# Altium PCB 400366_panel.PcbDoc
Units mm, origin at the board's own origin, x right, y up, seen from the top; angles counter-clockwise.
Board outline 266.08 x 131.72 mm, 4 copper layers (Top Layer, Mid-Layer 1, Mid-Layer 2, Bottom Layer), stack 1.516 mm thick; 4 components, 35 nets, 260 pads, 0 vias.
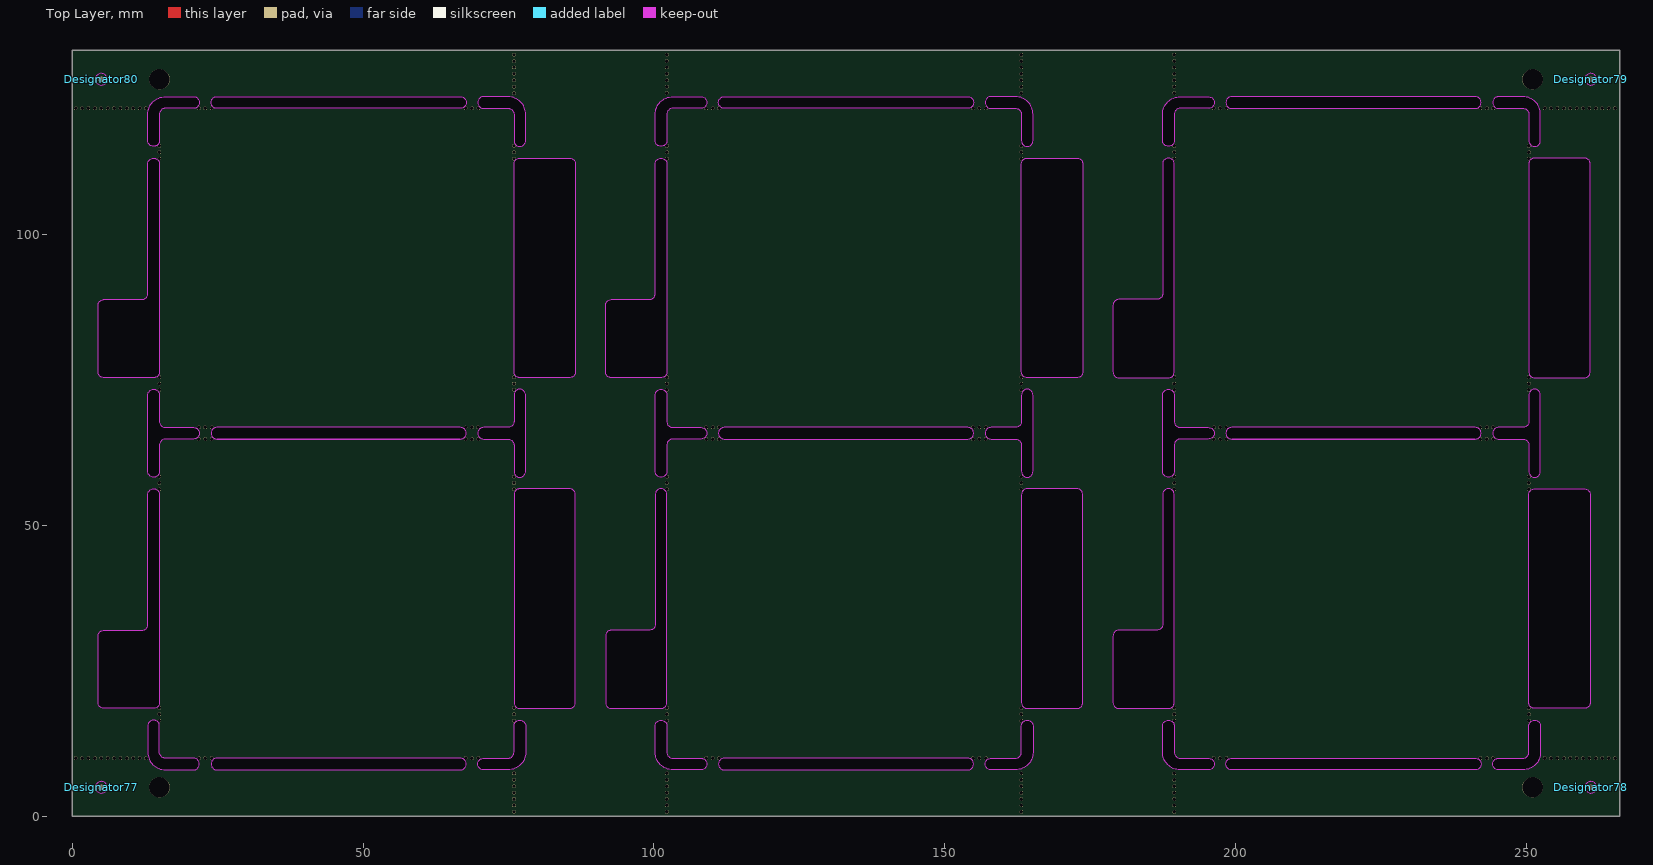
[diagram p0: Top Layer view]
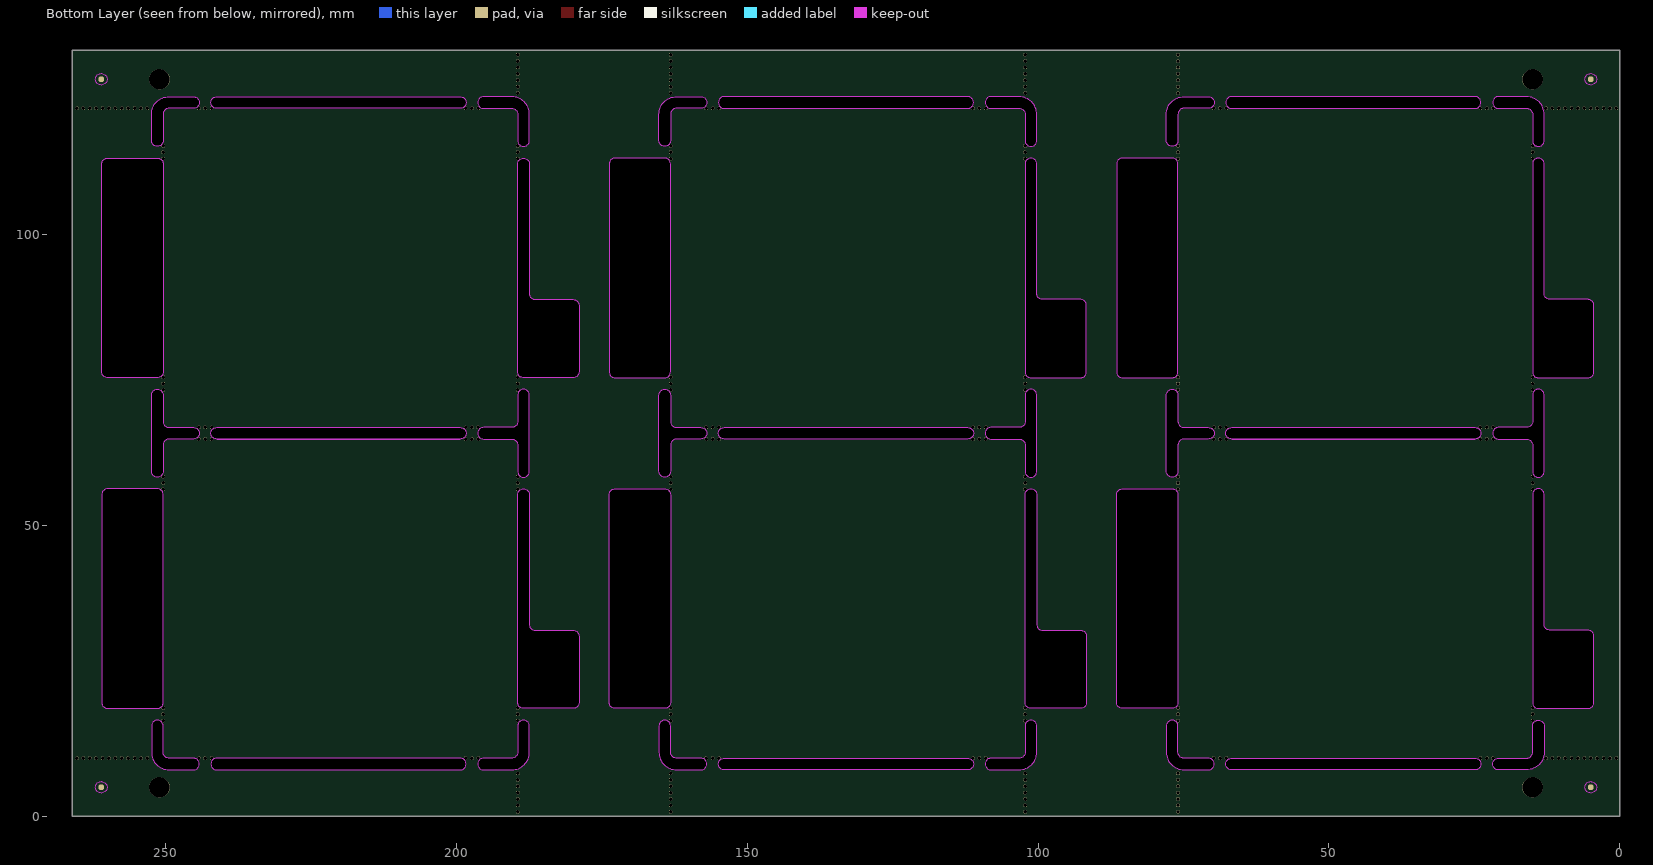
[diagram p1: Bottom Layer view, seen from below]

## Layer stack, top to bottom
Top Solder: solder mask 0.0381, SM-003, Dk 3.4
Top Layer: signal copper 0.0457
Dielectric1: prepreg 0.1626, FR-4, Dk 3.9
Mid-Layer 1: signal copper 0.035
Dielectric2: core 1.029, FR-4, Dk 3.9
Mid-Layer 2: signal copper 0.035
Dielectric3: prepreg 0.1626, FR-4, Dk 3.9
Bottom Layer: signal copper 0.0457
Bottom Solder: solder mask 0.0381, SM-003, Dk 3.4

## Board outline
0,0 266.075,0 266.075,131.725 0,131.725
cut-out: 187.476,116.172 187.476,120.712 cw(c190.492,120.712) 190.492,123.728 195.357,123.728 cw(c195.357,122.728) 195.357,121.728 190.492,121.728 ccw(c190.492,120.712) 189.476,120.712 189.476,116.172 cw(c188.476,116.172)
cut-out: 199.352,121.728 241.217,121.728 ccw(c241.217,122.728) 241.217,123.728 199.352,123.728 ccw(c199.352,122.728)
cut-out: 245.205,121.728 249.42,121.728 cw(c249.42,120.712) 250.436,120.712 250.436,116.172 ccw(c251.436,116.172) 252.436,116.172 252.436,120.712 ccw(c249.42,120.712) 249.42,123.728 245.205,123.728 ccw(c245.205,122.728)
cut-out: 199.352,64.864 241.217,64.864 ccw(c241.217,65.864) 241.217,66.864 199.352,66.864 ccw(c199.352,65.864)
cut-out: 199.352,64.864 241.217,64.864
cut-out: 245.205,64.864 249.42,64.864 cw(c249.42,63.848) 250.436,63.848 250.436,59.308 ccw(c251.436,59.308) 252.436,59.308 252.436,72.418 ccw(c251.436,72.418) 250.436,72.418 250.436,67.88 cw(c249.42,67.88) 249.42,66.864 245.205,66.864 ccw(c245.205,65.864)
cut-out: 250.436,76.414 ccw(c251.436,76.414) 251.436,75.414 259.976,75.414 ccw(c259.976,76.414) 260.976,76.414 260.976,112.176 ccw(c259.976,112.176) 259.976,113.176 251.436,113.176 ccw(c251.436,112.176) 250.436,112.176
cut-out: 250.436,19.55 250.436,55.312 cw(c251.436,55.312) 251.436,56.312 259.976,56.312 cw(c259.976,55.312) 260.976,55.312 260.976,19.55 cw(c259.976,19.55) 259.976,18.55 251.436,18.55 cw(c251.436,19.55)
cut-out: 245.205,8 cw(c245.205,9) 245.205,10 249.42,10 ccw(c249.42,11.016) 250.436,11.016 250.436,15.554 cw(c251.436,15.554) 252.436,15.554 252.436,11.016 cw(c249.42,11.016) 249.42,8
cut-out: 199.352,8 cw(c199.352,9) 199.352,10 241.217,10 cw(c241.217,9) 241.217,8
cut-out: 187.476,11.016 187.476,15.554 cw(c188.476,15.554) 189.476,15.554 189.476,11.016 ccw(c190.492,11.016) 190.492,10 195.356,10 cw(c195.356,9) 195.356,8 190.492,8 cw(c190.492,11.016)
cut-out: 187.476,59.308 187.476,72.418 cw(c188.476,72.418) 189.476,72.418 189.476,67.88 ccw(c190.492,67.88) 190.492,66.864 195.356,66.864 cw(c195.356,65.864) 195.356,64.864 190.492,64.864 ccw(c190.492,63.848) 189.476,63.848 189.476,59.308 cw(c188.476,59.308)
cut-out: 178.936,19.55 ccw(c179.936,19.55) 179.936,18.55 188.476,18.55 ccw(c188.476,19.55) 189.476,19.55 189.476,55.312 ccw(c188.476,55.312) 187.476,55.312 187.476,33 cw(c186.476,33) 186.476,32 179.936,32 ccw(c179.936,31) 178.936,31
cut-out: 178.936,76.414 ccw(c179.936,76.414) 179.936,75.414 188.476,75.414 ccw(c188.476,76.414) 189.476,76.414 189.476,112.176 ccw(c188.476,112.176) 187.476,112.176 187.476,89.864 cw(c186.476,89.864) 186.476,88.864 179.936,88.864 ccw(c179.936,87.864) 178.936,87.864
cut-out: 157.967,64.864 162.182,64.864 cw(c162.182,63.848) 163.198,63.848 163.198,59.308 ccw(c164.198,59.308) 165.198,59.308 165.198,72.419 ccw(c164.198,72.419) 163.198,72.419 163.198,67.88 cw(c162.182,67.88) 162.182,66.864 157.967,66.864 ccw(c157.967,65.864)
cut-out: 112.114,64.864 153.979,64.864 ccw(c153.979,65.864) 153.979,66.864 112.114,66.864 ccw(c112.114,65.864)
cut-out: 70.729,64.864 74.944,64.864 cw(c74.944,63.848) 75.96,63.848 75.96,59.308 ccw(c76.96,59.308) 77.96,59.308 77.96,72.419 ccw(c76.96,72.419) 75.96,72.419 75.96,67.88 cw(c74.944,67.88) 74.944,66.864 70.729,66.864 ccw(c70.729,65.864)
cut-out: 24.876,64.864 66.741,64.864 ccw(c66.741,65.864) 66.741,66.864 24.876,66.864 ccw(c24.876,65.864)
cut-out: 100.238,59.308 100.238,72.419 cw(c101.238,72.419) 102.238,72.419 102.238,67.88 ccw(c103.254,67.88) 103.254,66.864 108.118,66.864 cw(c108.118,65.864) 108.118,64.864 103.254,64.864 ccw(c103.254,63.848) 102.238,63.848 102.238,59.308 cw(c101.238,59.308)
cut-out: 92.698,75.415 cw(c92.698,76.415) 91.698,76.415 91.698,87.864 cw(c92.698,87.864) 92.698,88.864 99.238,88.864 ccw(c99.238,89.864) 100.238,89.864 100.238,112.176 cw(c101.238,112.176) 102.238,112.176 102.238,76.415 cw(c101.238,76.415) 101.238,75.415
cut-out: 100.238,116.172 100.238,120.712 cw(c103.254,120.712) 103.254,123.728 103.254,123.729 108.119,123.729 cw(c108.119,122.728) 108.119,121.728 103.254,121.728 ccw(c103.254,120.712) 102.238,120.712 102.238,116.172 cw(c101.238,116.172)
cut-out: 112.114,121.728 cw(c112.114,122.728) 112.114,123.729 112.114,123.728 153.979,123.729 cw(c153.979,122.728) 153.979,121.728
cut-out: 157.967,121.728 162.182,121.728 cw(c162.182,120.712) 163.198,120.712 163.198,116.172 ccw(c164.198,116.172) 165.198,116.172 165.198,120.712 ccw(c162.182,120.712) 162.182,123.728 162.182,123.729 157.967,123.729 ccw(c157.967,122.728)
cut-out: 163.198,76.415 163.198,112.176 cw(c164.198,112.176) 164.198,113.176 172.738,113.176 cw(c172.738,112.176) 173.738,112.176 173.738,76.415 cw(c172.738,76.415) 172.738,75.415 164.198,75.415 cw(c164.198,76.415)
cut-out: 163.198,19.551 ccw(c164.198,19.551) 164.198,18.551 172.738,18.551 ccw(c172.738,19.551) 173.738,19.551 173.738,55.312 ccw(c172.738,55.312) 172.738,56.312 164.198,56.312 ccw(c164.198,55.312) 163.198,55.312
cut-out: 157.967,8 cw(c157.967,9) 157.967,10 162.182,10 ccw(c162.182,11.016) 163.198,11.016 163.198,15.555 cw(c164.198,15.555) 165.198,15.555 165.198,11.016 cw(c162.182,11.016) 162.182,8
cut-out: 112.114,8 153.979,8 ccw(c153.979,9) 153.979,10 112.114,10 ccw(c112.114,9)
cut-out: 100.238,11.016 100.238,15.555 cw(c101.238,15.555) 102.238,15.555 102.238,11.016 ccw(c103.254,11.016) 103.254,10 108.118,10 cw(c108.118,9) 108.118,8 103.254,8 cw(c103.254,11.016)
cut-out: 91.698,19.551 ccw(c92.698,19.551) 92.698,18.551 101.238,18.551 ccw(c101.238,19.551) 102.238,19.551 102.238,55.312 ccw(c101.238,55.312) 100.238,55.312 100.238,33 cw(c99.238,33) 99.238,32 92.698,32 ccw(c92.698,31) 91.698,31
cut-out: 70.729,8 cw(c70.729,9) 70.729,10 74.944,10 ccw(c74.944,11.016) 75.96,11.016 75.96,15.555 cw(c76.96,15.555) 77.96,15.555 77.96,11.016 cw(c74.944,11.016) 74.944,8
cut-out: 75.96,19.551 ccw(c76.96,19.551) 76.96,18.551 85.5,18.551 ccw(c85.5,19.551) 86.5,19.551 86.5,55.312 ccw(c85.5,55.312) 85.5,56.312 76.96,56.312 ccw(c76.96,55.312) 75.96,55.312
cut-out: 24.876,64.864 66.741,64.864
cut-out: 24.876,8 66.741,8 ccw(c66.741,9) 66.741,10 24.876,10 ccw(c24.876,9)
cut-out: 5.46,18.551 cw(c5.46,19.551) 4.46,19.551 4.46,31 cw(c5.46,31) 5.46,32 12,32 ccw(c12,33) 13,33 13,55.312 cw(c14,55.312) 15,55.312 15,19.551 cw(c14,19.551) 14,18.551
cut-out: 24.876,64.864 66.741,64.864
cut-out: 24.876,64.864 66.741,64.864
cut-out: 13,59.308 13,72.419 cw(c14,72.419) 15,72.419 15,67.88 ccw(c16.016,67.88) 16.016,66.864 20.88,66.864 cw(c20.88,65.864) 20.88,64.864 16.016,64.864 ccw(c16.016,63.848) 15,63.848 15,59.308 cw(c14,59.308)
cut-out: 5.46,75.415 cw(c5.46,76.415) 4.46,76.415 4.46,87.864 cw(c5.46,87.864) 5.46,88.864 12,88.864 ccw(c12,89.864) 13,89.864 13,112.176 cw(c14,112.176) 15,112.176 15,76.415 cw(c14,76.415) 14,75.415
cut-out: 13,116.172 13,120.712 cw(c16.016,120.712) 16.016,123.728 16.016,123.729 20.881,123.729 cw(c20.881,122.728) 20.881,121.728 16.016,121.728 ccw(c16.016,120.712) 15,120.712 15,116.172 cw(c14,116.172)
cut-out: 24.876,121.728 cw(c24.876,122.728) 24.876,123.729 24.876,123.728 66.741,123.729 cw(c66.741,122.728) 66.741,121.728
cut-out: 70.729,121.728 74.944,121.728 cw(c74.944,120.712) 75.96,120.712 75.96,116.172 ccw(c76.96,116.172) 77.96,116.172 77.96,120.712 ccw(c74.944,120.712) 74.944,123.728 74.944,123.729 70.729,123.729 ccw(c70.729,122.728)
cut-out: 75.96,76.415 75.96,112.176 cw(c76.96,112.176) 76.96,113.176 85.5,113.176 cw(c85.5,112.176) 86.5,112.176 86.5,76.415 cw(c85.5,76.415) 85.5,75.415 76.96,75.415 cw(c76.96,76.415)
cut-out: 16.016,10 cw(c16.016,11.016) 15,11.016 15,15.555 ccw(c14,15.555) 13,15.555 13,11.016 ccw(c16.016,11.016) 16.016,8 20.88,8 ccw(c20.88,9) 20.88,10

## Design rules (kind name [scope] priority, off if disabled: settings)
Clearance ANT_Clerance [InNet('ANT1') or InNet('ANT2') or InNet('TRX') or InNet('RF_O1') or InNet('RF_O2') or InNet('RF_I') or InNet('A') or InNet('ANT') vs (InNamedPolygon('Top_Layer-GND')) or (InNamedPolygon('Bottom_Layer-GND')) or (InNamedPolygon('Mid_Layer_1-GND')) or (InNamedPolygon('Mid_Layer_2-GND'))] p1: gap=0.721 ignorepadtopadclearanceinfootprint=FALSE
Clearance Polygon_Clearance [(InNamedPolygon('Top_Layer-GND')) or (InNamedPolygon('Bottom_Layer-GND')) or (InNamedPolygon('Mid_Layer_1-GND')) or (InNamedPolygon('Mid_Layer_2-GND'))] p2: gap=0.254 ignorepadtopadclearanceinfootprint=FALSE except(0: Arc-Hole Track-Hole SMDPad-Hole THPad-Hole Via-Hole Fill-Hole Poly-Hole Region-Hole Text-Hole)
Clearance [All] p3: gap=0.152 ignorepadtopadclearanceinfootprint=FALSE except(0: Arc-Hole Track-Hole SMDPad-Hole THPad-Hole Via-Hole Fill-Hole Poly-Hole Region-Hole Text-Hole)
ComponentClearance [All] p1 off: gap=0.254 collisioncheckmode=3 verticalgap=0.254 showdistances=FALSE
DiffPairsRouting [All] p1: maxlimit=0.254 minlimit=0.15 mostfreqgap=0.254 toplayer_maxgap=0.15 toplayer_prefgap=0.15 toplayer_minwidth=0.203 toplayer_maxwidth=0.381 toplayer_prefwidth=0.381 midlayer1_mingap=0.254 midlayer1_minwidth=0.203 midlayer1_maxwidth=0.381 midlayer1_prefwidth=0.381 midlayer2_mingap=0.254 midlayer2_minwidth=0.203 midlayer2_maxwidth=0.381 midlayer2_prefwidth=0.381 bottomlayer_maxgap=0.15 bottomlayer_prefgap=0.15 bottomlayer_minwidth=0.203 bottomlayer_maxwidth=0.381 bottomlayer_prefwidth=0.381 maxuncoupledlength=12.7
FabricationTestPointUsage TestPointUsage [All] p1: valid=0 allowmultiple=FALSE
FabricationTestpoint Testpoint [All] p1: side=3 testpointundercomponent=TRUE minsize=1.016 maxsize=2.54 preferedsize=1.524 minholesize=0 maxholesize=1.016 preferedholesize=0.813 testpointgrid=0.025 allowsidetop=TRUE allowsidebottom=TRUE usegrid=TRUE gridtolerance=0
Height [All] p1 off: minheight=0 maxheight=25.4 prefheight=12.7
HoleSize [All] p1: absolutevalues=TRUE maxlimit=5 minlimit=0.3 maxpercent=80.000 minpercent=20.000
MinimumAnnularRing [All] p1 off: minimumring=0.152
MinimumSolderMaskSliver [All] p1: minsoldermaskwidth=0.08
PolygonConnect PolygonConnect_1 [isVia and innet(gnd) or HasFootprint('COAXIAL-SWF')] p1: connectstyle=Direct reliefconductorwidth=0.254 reliefentries=4 polygonreliefangle="90 Angle" airgapwidth=0.254
PolygonConnect [All] p2: connectstyle=Relief reliefconductorwidth=0.254 reliefentries=4 polygonreliefangle="90 Angle" airgapwidth=0.254
RoutingVias [All] p1: holewidth=0.305 width=0.61 viastyle="Through Hole" minholewidth=0.305 minwidth=0.61 maxholewidth=0.711 maxwidth=1.27
SilkToSilkClearance [All] p1: silktosilkclearance=0
SilkToSolderMaskClearance SilkscreenOverComponentPads [IsPad] p1: minsilkscreentomaskgap=0.254 clearancetoexposedcopper=TRUE
SolderMaskExpansion [All] p1: expansion=0.076 istentingtop=FALSE
Width [All] p1: maxlimit=2.54 minlimit=0.152 preferedwidth=0.152
21 further rules are at their usual default settings.

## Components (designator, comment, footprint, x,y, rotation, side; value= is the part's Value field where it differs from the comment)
Designator77 "Comment" Fiducial 5,5 r90 top
Designator78 "Comment" Fiducial 261.075,5 r90 top
Designator79 "Comment" Fiducial 261.075,126.725 r270 top
Designator80 "Comment" Fiducial 5,126.725 r270 top

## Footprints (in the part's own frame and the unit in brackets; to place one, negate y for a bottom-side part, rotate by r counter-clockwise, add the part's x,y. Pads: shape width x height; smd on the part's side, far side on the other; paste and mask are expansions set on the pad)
Fiducial [mm] "Fiducial Mark"
  round 1 smd paste+0 mask+0.5: 0(0,0)
  round 1 smd far side paste+0 mask+0.5: 0(0,0)
  Top Layer keep-out circle w0.01: c0,0 r1
  Bottom Layer keep-out circle w0.01: c0,0 r1

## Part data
Designator77 Designator78 Designator79 Designator80: library part Fid-Mark

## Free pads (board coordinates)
  round 3.5 hole 3.5 unplated: 3(14.999,4.999) 3(14.999,126.726) 3(251.076,126.726) 3(251.076,4.999)
  round 0.6 hole 0.6 unplated: 4(0.604,10) 4(0.604,121.724) 4(1.704,10) 4(1.704,121.724) 4(2.804,10) 4(2.804,121.724) 4(3.904,10) 4(3.904,121.724) 4(5.004,10) 4(5.004,121.724) 4(6.103,10) 4(6.103,121.724) 4(7.203,10) 4(7.203,121.724) 4(8.303,10) 4(8.303,121.724) 4(9.403,10) 4(9.403,121.724) 4(10.503,10) 4(10.503,121.724) 4(11.602,10) 4(11.602,121.724) 4(12.702,10) 4(12.702,121.724) 4(15,16.449) 4(15,17.549) 4(15,18.649) 4(15,56.214) 4(15,57.314) 4(15,58.414) 4(15,73.313) 4(15,74.413) 4(15,75.513) 4(15,113.078) 4(15,114.178) 4(15,115.278) 4(21.775,10) 4(21.775,64.864) 4(21.775,66.864) 4(21.775,121.724) 4(22.874,10) 4(22.874,64.864) 4(22.874,66.864) 4(22.874,121.724) 4(23.974,10) 4(23.974,64.864) 4(23.974,66.864) 4(23.974,121.724) 4(67.635,10) 4(67.636,64.864) 4(67.636,66.864) 4(67.636,121.724) 4(68.735,10) 4(68.735,64.864) 4(68.735,66.864) 4(68.735,121.724) 4(69.835,10) 4(69.835,64.864) 4(69.835,66.864) 4(69.835,121.724) 4(75.96,0.778) 4(75.96,1.878) 4(75.96,2.978) 4(75.96,4.077) 4(75.96,5.177) 4(75.96,6.277) 4(75.96,7.377) 4(75.96,16.449) 4(75.96,17.549) 4(75.96,18.649) 4(75.96,56.214) 4(75.96,57.314) 4(75.96,58.414) 4(75.96,73.313) 4(75.96,74.413) 4(75.96,75.513) 4(75.96,113.078) 4(75.96,114.178) 4(75.96,115.278) 4(75.96,124.349) 4(75.96,125.449) 4(75.96,126.549) 4(75.96,127.648) 4(75.96,128.748) 4(75.96,129.848) 4(75.96,130.948) 4(102.238,0.778) 4(102.238,1.878) 4(102.238,2.978) 4(102.238,4.077) 4(102.238,5.177) 4(102.238,6.277) 4(102.238,7.377) 4(102.238,16.449) 4(102.238,17.549) 4(102.238,18.649) 4(102.238,56.214) 4(102.238,57.314) 4(102.238,58.414) 4(102.238,73.313) 4(102.238,74.413) 4(102.238,75.513) 4(102.238,113.078) 4(102.238,114.178) 4(102.238,115.278) 4(102.238,124.349) 4(102.238,125.449) 4(102.238,126.549) 4(102.238,127.648) 4(102.238,128.748) 4(102.238,129.848) 4(102.238,130.948) 4(109.013,10) 4(109.013,64.864) 4(109.013,66.864) 4(109.013,121.724) 4(110.112,10) 4(110.112,64.864) 4(110.112,66.864) 4(110.112,121.724) 4(111.212,10) 4(111.212,64.864) 4(111.212,66.864) 4(111.212,121.724) 4(154.873,10) 4(154.874,64.864) 4(154.874,66.864) 4(154.874,121.724) 4(155.973,10) 4(155.973,64.864) 4(155.973,66.864) 4(155.973,121.724) 4(157.073,10) 4(157.073,64.864) 4(157.073,66.864) 4(157.073,121.724) 4(163.198,0.778) 4(163.198,1.878) 4(163.198,2.978) 4(163.198,4.077) 4(163.198,5.177) 4(163.198,6.277) 4(163.198,7.377) 4(163.198,16.449) 4(163.198,17.549) 4(163.198,18.649) 4(163.198,56.214) 4(163.198,57.314) 4(163.198,58.414) 4(163.198,73.313) 4(163.198,74.413) 4(163.198,75.513) 4(163.198,113.078) 4(163.198,114.178) 4(163.198,115.278) 4(163.198,124.349) 4(163.198,125.449) 4(163.198,126.549) 4(163.198,127.648) 4(163.198,128.748) 4(163.198,129.848) 4(163.198,130.948) 4(189.476,0.778) 4(189.476,1.877) 4(189.476,2.977) 4(189.476,4.077) 4(189.476,5.177) 4(189.476,6.277) 4(189.476,7.376) 4(189.476,16.449) 4(189.476,17.549) 4(189.476,18.648) 4(189.476,56.214) 4(189.476,57.313) 4(189.476,58.413) 4(189.476,73.313) 4(189.476,74.413) 4(189.476,75.512) 4(189.476,113.078) 4(189.476,114.178) 4(189.476,115.277) 4(189.476,124.349) 4(189.476,125.448) 4(189.476,126.548) 4(189.476,127.648) 4(189.476,128.748) 4(189.476,129.848) 4(189.476,130.947) 4(196.251,10) 4(196.251,64.864) 4(196.251,66.864) 4(196.251,121.724) 4(197.35,10) 4(197.35,64.864) 4(197.35,66.864) 4(197.35,121.724) 4(198.45,10) 4(198.45,64.864) 4(198.45,66.864) 4(198.45,121.724) 4(242.111,10) 4(242.112,64.864) 4(242.112,66.864) 4(242.112,121.724) 4(243.211,10) 4(243.211,64.864) 4(243.211,66.864) 4(243.211,121.724) 4(244.311,10) 4(244.311,64.864) 4(244.311,66.864) 4(244.311,121.724) 4(250.436,16.449) 4(250.436,17.549) 4(250.436,18.648) 4(250.436,56.214) 4(250.436,57.313) 4(250.436,58.413) 4(250.436,73.313) 4(250.436,74.413) 4(250.436,75.512) 4(250.436,113.078) 4(250.436,114.177) 4(250.436,115.277) 4(253.158,10) 4(253.159,121.724) 4(254.258,10) 4(254.258,121.724) 4(255.358,10) 4(255.358,121.724) 4(256.458,10) 4(256.458,121.724) 4(257.558,10) 4(257.558,121.724) 4(258.657,10) 4(258.658,121.724) 4(259.757,10) 4(259.757,121.724) 4(260.857,10) 4(260.857,121.724) 4(261.957,10) 4(261.957,121.724) 4(263.057,10) 4(263.057,121.724) 4(264.157,10) 4(264.157,121.724) 4(265.256,10) 4(265.257,121.724)

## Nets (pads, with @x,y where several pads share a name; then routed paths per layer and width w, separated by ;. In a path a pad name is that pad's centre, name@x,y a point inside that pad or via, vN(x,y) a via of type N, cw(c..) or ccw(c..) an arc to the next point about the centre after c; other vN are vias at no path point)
A0: 
A1: 
A2: 
A3: 
A4: 
A5: 
ANT1: 
ANT2: 
ANT_SEL: 
AREF: 
"D0 (RX)": 
"D1 (TX)": 
D6: 
D7: 
D8: 
"D10 (SS)": 
"D11 (MOSI)": 
"D12 (MISO)": 
"D13 (SCK)": 
GND: 
MODE: 
NetP1_5: 
NetP1_8: 
PDN: 
RESET: 
RF_I: 
RF_O1: 
RF_O2: 
RX_EN: 
SCL: 
SDA: 
TRX: 
TX_EN: 
VDD: 
VDD_nRF: 
pads on no net: Designator77.0 Designator78.0 Designator79.0 Designator80.0

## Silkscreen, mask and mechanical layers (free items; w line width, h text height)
Mechanical 21 (Mech21):
  drawing of 304 lines, arcs and shapes, not listed

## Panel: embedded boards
"400366.PcbDoc" at 15,10, 2 rows x 3 columns, spacing 56.864 x 87.238, rotation 0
